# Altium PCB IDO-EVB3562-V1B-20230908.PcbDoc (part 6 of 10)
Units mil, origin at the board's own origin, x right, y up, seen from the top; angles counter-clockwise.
Board outline 5314.96 x 3543.31 mil, 4 copper layers (TOP, L2-VCC, L3-GND, BOTTOM), stack 28.8 mil thick; 747 components, 560 nets, 2514 pads, 1964 vias.
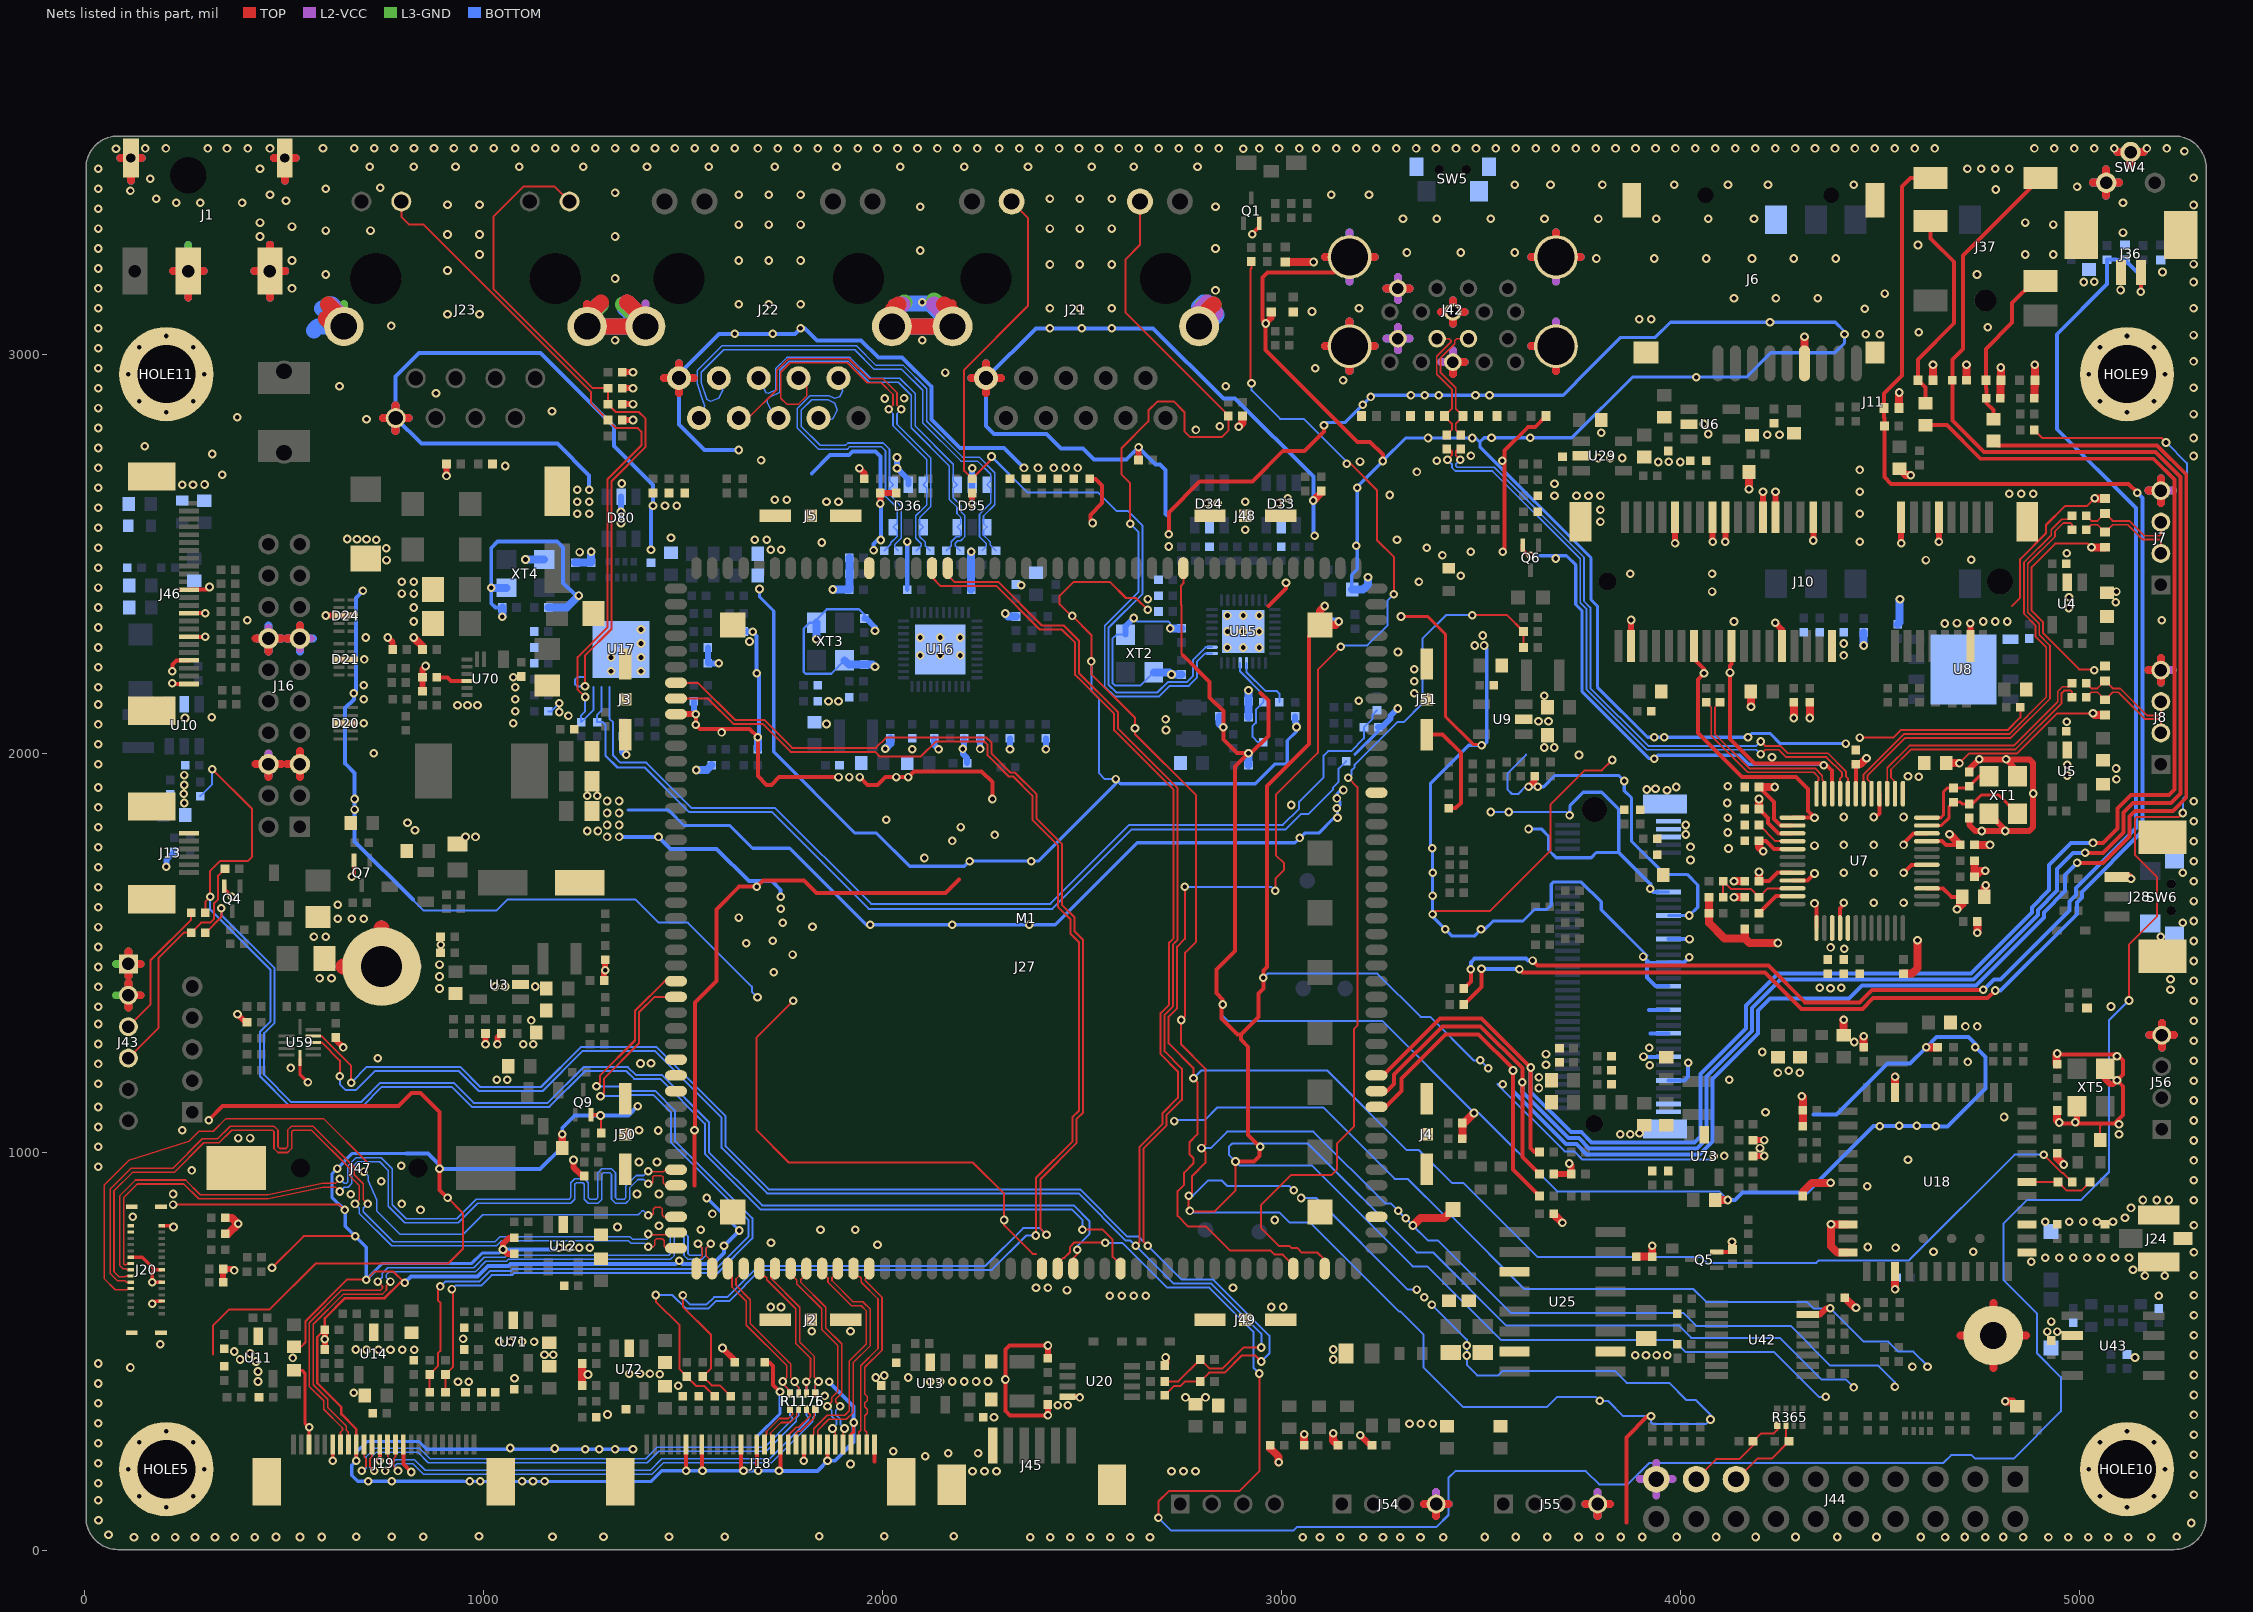
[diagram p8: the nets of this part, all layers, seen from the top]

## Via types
v1: diameter 21.65, hole 11.81, TOP to BOTTOM, 1964 vias

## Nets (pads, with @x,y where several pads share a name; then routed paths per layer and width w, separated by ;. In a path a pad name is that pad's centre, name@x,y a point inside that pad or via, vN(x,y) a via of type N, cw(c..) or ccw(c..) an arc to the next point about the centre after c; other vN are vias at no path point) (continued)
GND: (continued)
  other v1: 124.13,34.53 177,34.53 227,34.53 277,34.53 327,34.53 377,34.53 427,34.53 480,35 540,35 595,35 2371.05,34.53 2421.05,34.53 2471.05,34.53 2521.05,34.53 2571.05,34.53 2621.05,34.53 2671.05,34.53 3054.05,34.53 3097.05,34.53 3148,34.53 3205.25,34.53 3255.05,34.53 3298.05,34.53 3349,34.53 3406.25,34.53 3510,35 3588,35 3667,35 3745,35 3798,35 3851,35 3905,35 3991,35 4090,35 4189,35 4289,35 4394,35 4492,35 4603.11,35.17 4664.06,34.53 4713,35 4764.47,34.53 4810,35 4859.59,34.77 4923.11,34.53 4973.11,34.53 5023.11,34.53 5073.11,34.53 5123.11,34.53 5180.67,34.53 681,36 770,36 849,36 1173,36 1301,36 1465,36 1605,36 5245,36 989,37 1842,37 2005,37 2179,37 59.98,40.63 5281,70 34.99,77 34.53,127 5287.83,141.12 34.53,170 5287.83,191.12 2226,200 2256,200 2286,200 2725,200 2755,200 2785,200 1920,218 34.53,220 2107.72,237.28 5287.83,241.12 2165,245 2240,245 2027,250 1179,257 1067,258 34.53,270 5287.83,291.12 3321.35,318.65 3350,318.65 3380,318.65 34.53,320 2280,335 5287.83,341.12 1311,342 2440,365 2465,365 34.53,370 2760,385 2810,385 1855.47,388.7 5287.83,391.12 675,397 1488.67,414.39 34.53,420 936.32,424.4 962.97,424.4 435,425 2120,425 2145,425 2175,425 2205,425 2235,425 2265,425 1078,433 1983.32,435 2065,435 2005,440 5287.83,441.12 1442,443 1365.65,444.12 1392.3,444.12 1417.3,444.12 435,450 115,460 4582.2,462.01 34.53,470 430,475 390,480 3130,480 522,484 5140,485 3887.52,490.89 3914.18,490.88 3940.83,490.88 3967.49,490.68 5287.83,491.12 1153,492 1175,492 415,495 375,500 680,505 706.99,504.58 736.99,504.58 766.99,504.58 796.67,504.58 826.67,504.58 3130,505 190,518 1040,525 1066.99,524.58 1096.99,524.58 1126.99,524.58 949,532 5287.83,541.12 4920,550 4945,550 1823,551 1920,551 4930,575 5287.83,591.12 1720,611.58 1746,611.58 2975,611.58 3005,611.58 3358.48,636.38 2570,640 2600,640 2630,640 2660,640 5200,640 5287.83,641.12 2463,654 2385,660 2415,660 2879,660 5165,690 5215,690 5287.83,691.12 5135,705 4880,725 4915,735 4950,735 4985,735 5020,735 5055,735 5090,735 5125,735 5287.83,748.67 4635,750 4735,750 1215,760 1240,760 1266.79,760.14 4540,760 4470,762 1988,768 1721,773 1545,805 1845,805 1931.93,805 1336,812 1440,815 5287.83,816.39 4915,825 4975,825 5010,825 5045,825 5085,825 2984,829.67 5115,835 121,838 1574,845 842.17,855 5130,860 795,870 5287.15,879.12 5160,880 5195,880 5225,880 667.12,894.32 222.01,894.95 1385,895 1440,895 4469,914 743.69,926.98 5287.15,929.12 269,954 34.53,963 794.26,965.74 1390,975 1435,975 5287.15,979.12 4571,981 4110.37,990.37 4200,1010 34.53,1013 5287.15,1029.12 385,1035 415,1035 3850,1045 3875,1045 5100,1045 3898,1047 1438,1054 245,1055 1390,1055 34.53,1063 4549,1066 4593,1066 5100,1070 4990,1075 5287.15,1079.12 4812,1088 4214,1100 34.53,1113 5287.15,1129.12 3645.86,1160.68 34.53,1171 5287.15,1179.12 1033.35,1181.47 1060,1181.47 4123,1181 3645.86,1187.34 4245,1199 4300,1199 4272,1204 517,1211 3923.63,1217.35 3663.7,1219 34.53,1221 1393.55,1221.9 1420.19,1222.55 4721,1226 5287.15,1229.12 735,1235 5095,1240 3663.7,1245.65 4206,1251 3922.47,1261.67 1100,1270 1125,1270 34.53,1271 4436,1276 5287.15,1279.12 4715,1315 4745,1315 34.53,1321 5287.15,1329.12 1120,1330 34.53,1364 5080,1365 5287.15,1379.12 5229,1406.91 890,1410 4376.98,1411 4350,1411.6 4404.04,1411.6 34.53,1414 1030,1415 1055,1415 1130,1415 5287.15,1429.12 5229,1433.57 589.25,1435.77 619.25,1435.77 890,1440 1727.4,1450.94 34.53,1464 890,1470 5287.15,1479.12 1775,1495 34.53,1514 893,1520 1658.62,1523.19 5287.15,1529.12 1725.27,1530 575,1540 605,1540 5205,1540 34.53,1564 1825,1565 1750.12,1575 5260,1575 5287.15,1579.12 635,1585 670,1585 700,1585 1640,1587.83 1745,1610 34.53,1614 635,1620 4485,1625 4560,1625 5287.15,1629.12 34.53,1664 5287.15,1679.12 4410,1700 4485,1700 5260,1700 34.53,1714 5287.15,1729.12 4026,1732 2105.41,1737 4121,1761 34.53,1764 4026,1765 4336.7,1768.3 4410,1770 4485,1770 5287.15,1779.12 2175,1780 955,1790 980,1790 1310,1790 2281.5,1795 4014,1796 4119,1801 1260,1805 1287,1805 828.5,1806.87 34.53,1814 2196.24,1814.69 1310,1820 1340,1820 4014,1820 809.65,1825.71 5287.15,1829.12 2009.43,1832.83 4119,1838 4410,1840 4560,1840 1310,1850 1340,1850 3139,1862 34.53,1864 3025,1870 250,1875 4118,1875 5287.15,1879.12 1310,1880 1340,1880 1260,1893 1285,1893 249,1898 3967,1907 3916,1909 3938,1911 34.53,1914 3990,1915 3643,1916 4119,1917 250,1920 5093.53,1934.47 1916.65,1940 4970,1944.02 250,1945 5092.72,1961.69 4970,1970.67 34.53,1972 4230,1990 3746.33,1995.33 725,2000 2075,2010 3659,2014 3684,2014 34.53,2022 1597,2052 2711,2058.06 34.53,2072 1860,2073 700,2075 1075,2075 4969,2079 3645,2080 3670,2080 2709.98,2084.69 252,2088 319,2090 1213,2094 1190.01,2103.32 1080,2105 935,2120 960,2120 985,2120 34.53,2122 1865,2130 1890,2130 3194.45,2131.6 700,2135 1080,2135 3659,2144 3333.42,2150 34.53,2165 1080,2165 700,2170 3333.42,2180 1075,2190 1320,2205 1395,2205 3333.42,2210 34.53,2215 701,2235 1320,2240 1395,2240 2095,2245 2145,2245 2195,2245 4410,2245 3292.68,2253.69 34.53,2265 2865,2265 2905,2265 2945,2265 3485,2270 1395,2275 4410,2275 1667,2280 705,2290 2095,2290 2145,2290 2195,2290 3505,2295 2865,2305 2905,2305 2945,2305 1395,2310 34.53,2315 4663,2325 4694,2326 825,2330 4135,2330 4760,2330 4790,2330 4820,2330 408.13,2333.04 5207,2333 2865,2345 2905,2345 2945,2345 4973.98,2364.03 34.53,2365 825,2365 5092,2378.39 2665.57,2386.24 4974.73,2390.67 795,2400 825,2400 4080,2405 5093.53,2405 34.53,2415 2348,2421 795,2430 825,2430 3345,2430 3450,2445 3875,2450 4080,2450 34.53,2465 757,2484 4616,2484 4730,2485 3688,2488 3404,2496 4969,2501 1241,2504 3475,2505 1720,2510 1746.65,2510 756,2514 34.53,2515 3365,2515 2718,2518 3188,2520 1848,2528 4450,2530 731,2535 1680,2535 1710,2535 3290,2535 683,2536 707,2536 658.69,2536.69 1470,2540 2910,2560 34.53,2565 3800,2580 1235,2600 1265,2600 4450,2600 3800,2610 34.53,2615 1455,2620 1484.4,2620 2813.45,2626.58 2840.11,2626.64 2992.39,2626.58 1235,2630 1265,2630 1860,2630 1890,2630 2910,2630 1730,2635 1760,2635 3015.93,2639.07 3685,2645 3740,2645 3770,2645 3800,2645 3272,2647 4825,2650 4855,2650 4885,2650 4450,2655 1235,2660 34.53,2665 245,2673 272,2673 301,2673.36 3685,2675 1347,2676 345,2698 3340,2705 4450,2710 34.53,2715 2390,2715 2430,2715 2460,2715 2490,2715 1055,2720 3945,2730 3971.65,2730.2 4000,2730 3197.22,2730.87 3390,2733.18 3554,2733 1696,2734 3795,2740 3825,2740 3855,2740 3475.41,2745.24 5287,2745 320,2750 34.53,2765 151,2769 5287,2790 4218,2798 4249,2798 4070,2800 3802,2803 2786.05,2810.32 34.53,2815 2845.64,2819.36 4059.33,2825 707,2837 383,2842 5287,2850 1172,2857 34.53,2865 2006,2889 2054.48,2890 881,2902 34.53,2915 5287,2916 639,2920 2861,2920 3155,2935 2158,2954 34.53,2965 3085,2965 5287,2982 34.53,3015 5287,3048 4465,3050 4500,3050 4598,3055 34.53,3065 4771,3068 769,3071 3897.26,3087.74 3927.26,3087.74 910,3100 990,3100 3077,3107 4463,3114 34.53,3115 2420,3115 2495,3115 2575,3115 3195,3115 5287,3115 1640,3125 1715,3125 1795,3125 4135,3140 4240,3140 4345,3140 4513,3152 5104,3161 34.53,3165 520,3165 5012,3181 5287,3181 5038,3182 4744,3200 5209,3206 910,3210 34.53,3215 2420,3225 2495,3225 2575,3225 5287,3226 520,3235 1640,3235 1715,3235 1795,3235 3790,3240 3935,3240 4065,3240 4180,3240 4285,3240 4390,3240 990,3250 4865,3250 4935,3250 3315,3255 3450,3255 3585,3255 34.53,3265 4596,3274 440,3295 910,3300 990,3300 5110,3305 717,3310 34.53,3315 2420,3315 2495,3315 2575,3315 520,3320 1640,3325 1715,3325 1795,3325 4935,3325 440,3330 4865,3330 3305,3340 3390,3340 3525,3340 3660,3340 3795,3340 3940,3340 4070,3340 4185,3340 34.53,3365 5287,3374 910,3375 990,3375 230,3380 290,3380 395,3380 5110,3380 505,3385 180,3390 2420,3390 2495,3390 2575,3390 465,3400 1640,3400 1715,3400 1795,3400 3125,3400 3220,3400 115,3410 4791,3413 34.53,3415 741,3417 4995,3420 3585,3425 3675,3425 3805,3425 3985,3425 4120,3425 4220,3425 4435,3425 165,3440 5287,3442 34.53,3465 440,3465 4720,3465 4755,3465 4790,3465 4825,3465 5264,3509 79,3515 2905,3515 152,3516 204,3516 309,3516 357,3516 409,3516 465,3516 2945,3516 2995,3516 3045,3516 3088,3516 3138,3516 3188,3516 3238,3516 3288,3516 3338,3516 3388,3516 3438,3516 3488,3516 3538,3516 3588,3516 3638,3516 3688,3516 3738,3516 3788,3516 3838,3516 3888,3516 3938,3516 3988,3516 4038,3516 4088,3516 4138,3516 4188,3516 4238,3516 4288,3516 4338,3516 4388,3516 4438,3516 4488,3516 4538,3516 4588,3516 4638,3516 4888,3516 4938,3516 4988,3516 5038,3516 5088,3516 5170,3516 5220,3516
GND_EARTH: HOLE5.1 HOLE9.1 HOLE10.1 HOLE11.1 J21.SH1 J21.SH2 J22.SH1 J22.SH2 J23.13 J23.14 | length 3703.1
  TOP w20: J23.13@1259.92,3094.92 1259.92,3126.14 ; J22.SH2@2023.9,3108.9 2023.9,3126.9 ; J21.SH1@2176.1,3103.9 2176.1,3126.9
  TOP w40: 605,3090 625.08,3069.92 J23.14@650.08,3069.92 650.08,3084.92 610,3125 ; J23.13@1259.92,3069.92 1259.92,3094.92 1295,3130 ; J23.13@1259.92,3069.92 J22.SH1@1406.1,3069.9 1406.1,3083.9 1360,3130 ; 2040,3125 2023.9,3108.9 J22.SH2@2023.9,3069.9 J21.SH1@2176.1,3069.9 2176.1,3103.9 2155,3125 ; J21.SH2@2793.9,3069.9 2793.9,3088.9 2830,3125
  L2-VCC w20: J22.SH1@1406.1,3083.9 1406.1,3126.9
  L2-VCC w40: 615,3125 650.08,3089.92 J23.14@650.08,3069.92 ; 1290,3125 1259.92,3094.92 J23.13@1259.92,3069.92 J22.SH1@1406.1,3069.9 1406.1,3083.9 1360,3130 ; 2050,3125 2023.9,3098.9 J22.SH2@2023.9,3069.9 J21.SH1@2176.1,3069.9 2176.1,3078.9 2130,3125 ; 2815,3130 2793.9,3108.9 J21.SH2@2793.9,3069.9 2799.9,3069.9 2835,3105
  L3-GND w20: J23.14@650.08,3084.92 650.08,3126.14 ; J21.SH2@2793.9,3088.9 2793.9,3126.9
  L3-GND w40: 605,3090 625.08,3069.92 J23.14@650.08,3069.92 650.08,3084.92 610,3125 ; 1295,3125 1259.92,3089.92 J23.13@1259.92,3069.92 J22.SH1@1406.1,3069.9 1405.1,3069.9 1350,3125 ; 2055,3130 2023.9,3098.9 J22.SH2@2023.9,3069.9 J21.SH1@2176.1,3069.9 2176.1,3088.9 2130,3135 ; J21.SH2@2793.9,3069.9 2793.9,3088.9 2830,3125
  BOTTOM w20: J23.13@1259.92,3094.92 1259.92,3126.14 ; 1349.1,3069.9 J22.SH1@1400.1,3069.9 ; J22.SH2@2023.9,3098.9 2023.9,3126.9
  BOTTOM w40: 575,3060 584.92,3069.92 J23.14@640.08,3069.92 ; 595,3115 J23.14@640.08,3069.92 ; 620,3125 650.08,3094.92 J23.14@650.08,3069.92 J23.14@640.08,3069.92 ; 1290,3125 1259.92,3094.92 J23.13@1259.92,3069.92 J22.SH1@1406.1,3069.9 1400.1,3069.9 1355,3115 ; 2805,3130 2793.9,3118.9 J21.SH2@2793.9,3069.9 ; J21.SH2@2793.9,3069.9 2809.9,3069.9 2838.18,3098.18 2838.18,3099.6 2831.6,3106.18 2830.18,3106.18 J21.SH2@2793.9,3069.9 ; J22.SH2@2023.9,3069.9 2023.9,3098.9 2052.19,3127.19 2118.81,3127.19 J21.SH1@2176.1,3069.9 J22.SH2@2023.9,3069.9
  other v1: 1330,3035 2100,3035 2100,3130 2835,3160 1330,3190 605,3200 2095,3260 2835,3265 1330,3295 605,3310 2095,3370 2835,3370 1330,3405 605,3415 715,3470 825,3470 930,3470 1090,3470 1250,3470 1410,3470 1565,3470 1730,3470 1885,3470 2045,3470 2205,3470 2365,3470 2525,3470 2630,3470 2790,3470 597.82,3516.18 676,3516.18 726,3516.18 776,3516.18 826,3516.18 876,3516.18 926,3516.18 976,3516.18 1026,3516.18 1080,3516.18 1130,3516.18 1180,3516.18 1230,3516.18 1280,3516.18 1330,3516.18 1380,3516.18 1430,3516.18 1480,3516.18 1530,3516.18 1580,3516.18 1630,3516.18 1688,3516 1738,3516 1788,3516 1838,3516 1888,3516 1938,3516 1988,3516 2038,3516 2088,3516 2138,3516 2188,3516 2238,3516 2293,3516 2343,3516 2393,3516 2443,3516 2493,3516 2543,3516 2593,3516 2643,3516 2693,3516 2743,3516 2793,3516 2843,3516
GPIO0_A5_D: M1.170 R429.2 R430.2 | length 2282.1
  TOP w5: M1.170@3108.86,707.87 3108.86,729.93 3090.78,748 3051.86,748 3040.86,759 3026,759 3021,764 2995,764 2949,810 2949,867 3024,942 3125,942 3140,957 3140,1022 3182,1064 3182,1308 3191,1317 3191,1915 v1(3168,1938) ; v1(3479,2346) 3566.28,2346 R429.2@3607.28,2305 R430.2@3607.28,2265
  BOTTOM w5: v1(3168,1938) 3176,1946 3176,1957 3184,1965 3184,1971 3291,2078 3307,2078 3353.5,2124.5 3353.5,2286.5 3413,2346 v1(3479,2346)
HOST_WAKE_BT_H: R237.2 R1174.1 U18.6 | length 175.3
  TOP w5: U18.6@4869.41,925 R237.2@4947.28,925 4968.28,904 5006.28,904 R1174.1@5027.28,925
HOST_WAKE_BT_H_GPIO0_A7_D: M1.168 R237.1 R1173.2 | length 5978.1
  TOP w5: v1(2758.33,1665) 2758.33,1534.33 2738.8,1514.8 2738.8,1360.86 2717.67,1339.74 2717.67,1272.75 2780,1210.42 v1(2780,1185) 2789.55,1175.45 2789.55,1044.56 2770,1025 2770,995 2780,985 2780,971.57 2756.68,948.25 2756.68,918.53 2740.03,901.87 2740.03,839.98 2766,814 2811,814 2872.07,752.93 2973.21,752.93 2983.21,742.93 3004.07,742.93 3030.12,716.88 M1.168@3030.12,707.87 ; R1173.2@2925,3232.28 2925,3215.13 2922.3,3212.42 2922.3,2930.22 v1(2925.51,2927) ; v1(2984.98,1655) 2984.98,1684.98 3007.39,1707.39 3007.39,1723.61 2986.65,1744.35 2986.65,1895.98 3091.64,2000.96 3091.64,2209.07 v1(3148.99,2266.43) ; v1(3164.36,2725.29) 3173.71,2725.29 3240,2659 3240,2534 3282,2492 v1(3282,2398) ; v1(4911.18,993.38) 4957.55,947 4960.72,947 R237.1@4982.72,925
  BOTTOM w5: v1(2758.33,1665) 2974.98,1665 v1(2984.98,1655) ; v1(2780,1185) 2800,1205 3114.57,1205 3314.57,1005 3345.3,1005 3428.12,922.17 3457.3,922.17 3642.79,736.67 4051.48,736.67 4065.95,722.21 4341.59,722.21 4347.6,728.22 4573.22,728.22 4838.38,993.38 v1(4911.18,993.38) ; v1(2925.51,2927) 2925.51,2909.49 2997,2838 3056.51,2838 3164.36,2730.15 v1(3164.36,2725.29) ; v1(3148.99,2266.43) 3152.56,2270 3216.04,2270 3266.75,2320.71 3266.75,2382.75 v1(3282,2398)
HP_DET_L_GPIO0_B3_D: M1.153 R455.1 | length 7025.2
  TOP w5: M1.153@2439.57,707.87 2439.57,721.57 2453,735 2456.11,735 2470.55,749.44 2470.55,762.59 2481.28,773.33 2558.32,773.33 v1(2559.02,772.63) ; v1(2692,83) 2692,124 2718,150 2895,150 2945,200 v1(2945,445) ; R455.1@4887.72,2810 4907.72,2790 5206.88,2790 v1(5218,2778.88) ; v1(5125,1380) 5125,1520 5195,1590 5195,1690 5140,1745 5140,1835 5145,1840 5250,1840 v1(5260,1850)
  BOTTOM w5: v1(2559.02,772.63) 2601.37,772.63 2714,660 2820,660 2930,550 2930,460 v1(2945,445) ; v1(2692,83) 2723.41,51.59 3031.14,51.59 3040.24,60.69 3389.69,60.69 3419.23,90.23 3419.23,183.23 3436.33,200.33 3763.71,200.33 3797.04,167 3869.07,167 3923.03,220.97 4660.11,220.97 4679.14,240 4730.8,240 4739.12,231.67 4827.49,231.67 4835.78,231.67 4954.15,350.05 4954.15,435.85 4895,495 4895,595 4810,680 4810,820 4870,880 5005,880 5075,950 5075,1330 v1(5125,1380) ; v1(5218,2778.88) 5270,2726.88 5270,1895 5260,1885 v1(5260,1850)
HP_SNS: J37.4 M1.11 R306.1 R316.2 | length 5192.3
  TOP w10: M1.11@3238.78,1152.76 3264.87,1152.76 3283,1170.89 3283,1193.98 3404.02,1315 3500,1315 3604.21,1210.79 v1(3604.21,1175.3) 3604.21,988.07 R306.1@3647.28,945 ; J37.4@4903.39,3441.73 4709,3247.34 4709,3013 4682.28,2986.28 R316.2@4682.28,2935 4682.28,2833.57 4761.15,2754.69 5191.52,2754.69 5253.62,2692.59 5253.62,1898.62 5230,1875 5135,1875 5111,1851 5111,1801 5060,1750 v1(5015,1750)
  BOTTOM w10: v1(3604.21,1175.3) 3604.21,1150.79 3720.24,1034.76 3745.81,1034.76 3771.68,1008.9 4042.23,1008.9 4066.06,1032.73 4066.06,1189.85 4180,1303.79 4180,1361.21 4251.22,1432.43 4735.11,1432.43 4896.44,1593.76 4896.44,1606.77 4945,1655.33 4945,1710 4985,1750 v1(5015,1750)
HPL_OUT: C215.1 C222.2 M1.10 | length 4508.9
  TOP w10: M1.10@3238.78,1113.39 3261.87,1113.39 3301,1152.52 3301,1183.87 3412.13,1295 3495,1295 3581.04,1208.96 v1(3581.04,1204.5) 3581.04,956.24 C215.1@3647.28,890.01 ; C222.2@4785,2782.44 4795.75,2771.69 5195.74,2771.69 5268.62,2698.81 5268.62,1888.62 5235,1855 5140,1855 5126,1841 5126,1790.57 5060.43,1725 v1(4995,1725)
  BOTTOM w10: v1(3581.04,1204.5) 3581.04,1152.74 3714.02,1019.76 3739.6,1019.76 3765.46,993.9 4048.44,993.9 4081.06,1026.51 4081.06,1183.63 4195,1297.57 4195,1355 4225,1385 4423,1385 4455.43,1417.43 4741.32,1417.43 4911.44,1587.55 4911.44,1600.56 4965,1654.12 4965,1695 v1(4995,1725)
HPL_OUT+: C222.1 D66.1 J37.2 R447.2 | length 420.1
  TOP w10: C222.1@4785,2837.56 4785,2860 4767.28,2877.72 R447.2@4767.28,2890 4767.28,2912.72 4766.1,2913.9 D66.1@4766.1,2935 4766.1,3013.1 4832,3079 4832,3128 4887.86,3183.86 J37.2@4903.39,3183.86
HPR_OUT: C219.1 C224.2 M1.12 | length 4476.1
  TOP w10: M1.12@3238.78,1192.13 3255.13,1192.13 3398,1335 3502.18,1335 v1(3625.09,1212.09) 3625.09,1191.26 3625.04,1191.21 3625.04,1010.01 3635.04,1000.01 C219.1@3647.28,1000.01 ; C224.2@4615,2822.44 4668.56,2822.44 4753,2738 5187,2738 5238.62,2686.38 5238.62,1908.62 5225,1895 5130,1895 5096,1861 5096,1811 5060,1775 v1(5035,1775)
  BOTTOM w10: v1(3625.09,1212.09) 3625.09,1210.09 3625.04,1210.04 3625.04,1151.17 3726.45,1049.76 3752.03,1049.76 3777.89,1023.9 4036.02,1023.9 4051.06,1038.94 4051.06,1196.06 4165,1310 4165,1367.43 4245,1447.43 4728.89,1447.43 4881.44,1599.98 4881.44,1612.99 4925,1656.55 4925,1720 4980,1775 v1(5035,1775)
HPR_OUT+: C224.1 D68.1 J37.3 | length 526.1
  TOP w10: C224.1@4615,2877.56 4615,2916.1 D68.1@4596.1,2935 4596.1,2987.1 4687,3078 4687,3231 4627.36,3290.64 J37.3@4627.36,3333.46
HUB_1V8: C303.2 C305.2 C310.2 C355.2 U7.3 U7.9 U7.26 U7.29 | length 571.4
  TOP w10: C310.2@4197.72,1780 4215,1780 4235.5,1759.5 U7.29@4281.7,1759.5 ; C305.2@4197.72,1915 4235,1877.72 4235,1835 4251.4,1818.6 U7.26@4281.7,1818.6 ; U7.3@4618.3,1661.1 4658.9,1661.1 4680,1640 C355.2@4707.44,1640 ; U7.9@4618.3,1779.2 4656.8,1779.2 4666,1770 4702,1770 C303.2@4702.28,1770
  TOP w20: C310.2@4197.72,1780 4197.72,1764.28 v1(4208,1754) ; C305.2@4197.72,1915 v1(4237,1915) ; v1(4675,1797) C303.2@4702,1770 ; v1(4694,1609) 4707.44,1622.44 C355.2@4707.44,1640
HUB_3V3: C304.2 C306.2 C307.1 C308.1 C309.1 C356.2 R45.2 R48.1 R434.1 R435.1 R436.1 R438.2 R439.2 U7.13 U7.19 U7.27 U7.32 U7.39 U7.41 | length 858.2
  TOP w10: C306.2@4197.72,1679 4223,1679 4244.5,1700.5 U7.32@4281.7,1700.5 ; C308.1@4197.72,1860 4220,1837.72 4220,1825 4246.1,1798.9 U7.27@4281.7,1798.9 ; C309.1@4440,1972.28 4440.2,1972.08 U7.19@4440.2,1898.3
  TOP w20: R45.2@4072.28,1639 R48.1@4072.28,1599 4072.28,1574.72 4111.28,1535.72 4162.28,1535.72 ; R438.2@4162.28,1559 4162.28,1535.72 ; C306.2@4197.72,1679 v1(4197.72,1702) ; C308.1@4197.72,1860 v1(4197.72,1885) ; v1(4245,1524) 4174,1524 4162.28,1535.72 ; C309.1@4440,1972.28 4452.28,1972.28 v1(4467,1987) ; R439.2@4560,1447.28 4581.28,1447.28 4595,1461 v1(4595,1531) ; R436.1@4737.72,1730 R435.1@4737.72,1690 4752.72,1705 v1(4765,1705) ; v1(4744.72,1550) R434.1@4744.72,1578
  other v1: 4411,1510 4377,1513 4598,1941 4571,1942
HUB_DM1: R49.1 U7.23 | length 444.5
  TOP w4.5: R49.1@4100,2127.28 4087.25,2114.53 4087.25,2047.75 4173.25,1961.75 4338.25,1961.75 4356.3,1943.7 4356.3,1933.7 4361.4,1928.6 U7.23@4361.4,1898.3
HUB_DM2: R37.1 U7.20 | length 1606.8
  TOP w4.5: v1(3448.33,2735.6) 3437.25,2746.68 3437.25,2757.25 3442.28,2762.28 R37.1@3450,2762.28 ; v1(4201.77,2029.34) 4212.84,2018.27 4251.17,2018.27 4269.94,1999.5 4370.5,1999.5 4415.4,1954.6 4415.4,1941.83 4420.5,1936.73 U7.20@4420.5,1898.3
  BOTTOM w4.5: v1(3448.33,2735.6) 3437.25,2724.53 3437.25,2720.03 3440.78,2716.5 3533.5,2716.5 3758.84,2491.16 3758.84,2381.16 3775,2365 3775,2163 3919.73,2018.27 4190.69,2018.27 v1(4201.77,2029.34)
HUB_DM2_2: D8.2 J42.11 R37.2 | length 324.4
  TOP w4.5: R37.2@3450,2797.72 3437.25,2810.47 3437.25,2826.15 D8.2@3456.1,2845 3437.25,2863.85 3437.25,2916.19 3399.5,2953.94 3399.5,2990.83 3434.75,3026.08 3434.75,3034.52 3439.25,3039.02 J42.11@3469.37,3039.02
HUB_DM3: R29.1 U7.17 | length 1124
  TOP w4.5: U7.17@4479.5,1898.3 4479.5,1924.5 4469.3,1934.7 4469.3,1943.3 4564.32,2038.32 4828.49,2038.32 4927,2136.83 4927,2269.59 4900.06,2296.53 4900.06,2324.66 4871.35,2353.37 4871.35,2474.35 4939.5,2542.5 4939.5,2556.06 4960.34,2576.9 4979.1,2576.9 4982.28,2573.72 R29.1@4982.28,2560
HUB_DM3_2: D4.2 J7.2 R29.2 | length 255.7
  TOP w4.5: R29.2@5017.72,2560 5030.47,2572.75 5046.15,2572.75 D4.2@5065,2553.9 5083.85,2572.75 5122.25,2572.75 5159.75,2535.25 5200.5,2535.25 5205,2530.75 J7.2@5205,2500.63
HUB_DM4: R32.1 U7.14 | length 630.9
  TOP w4.5: U7.14@4538.6,1898.3 4538.6,1928.4 4528.4,1938.6 4528.4,1958.96 4578.75,2009.32 4840.5,2009.32 4956,2124.82 4956,2150.56 4962.34,2156.9 4979.1,2156.9 4982.28,2153.72 R32.1@4982.28,2140
HUB_DM4_2: D6.2 J8.2 R32.2 | length 268.1
  TOP w4.5: R32.2@5017.72,2140 5030.47,2152.75 5046.15,2152.75 D6.2@5065,2133.9 5083.85,2152.75 5098.5,2152.75 5166,2085.25 5200.5,2085.25 5205,2080.75 J8.2@5205,2050.63
HUB_DP1: R50.1 U7.24 | length 444.5
  TOP w4.5: R50.1@4065,2127.28 4077.75,2114.53 4077.75,2043.81 4169.31,1952.25 4334.31,1952.25 4346.8,1939.77 4346.8,1931.8 4341.7,1926.7 U7.24@4341.7,1898.3
HUB_DP2: R38.1 U7.21 | length 1606.8
  TOP w4.5: R38.1@3415,2762.28 3422.72,2762.28 3427.75,2757.25 3427.75,2746.68 v1(3416.67,2735.6) ; v1(4201.77,1997.69) 4212.84,2008.77 4247.23,2008.77 4266,1990 4366.56,1990 4405.9,1950.67 4405.9,1941.83 4400.8,1936.73 U7.21@4400.8,1898.3
  BOTTOM w4.5: v1(3416.67,2735.6) 3427.75,2724.53 3427.75,2716.09 3436.84,2707 3529.56,2707 3749.34,2487.23 3749.34,2377.23 3765.5,2361.06 3765.5,2159.06 3915.8,2008.77 4190.69,2008.77 v1(4201.77,1997.69)
HUB_DP2_2: D9.1 J42.12 R38.2 | length 324.4
  TOP w4.5: J42.12@3390.63,3039.02 3420.75,3039.02 3425.25,3034.52 3425.25,3030.01 3390,2994.76 3390,2950 3427.75,2912.25 3427.75,2863.85 D9.1@3408.9,2845 3427.75,2826.15 3427.75,2810.47 R38.2@3415,2797.72
HUB_DP3: R30.1 U7.18 | length 1124.1
  TOP w4.5: U7.18@4459.8,1898.3 4459.8,1947.23 4560.38,2047.82 4824.55,2047.82 4917.5,2140.77 4917.5,2265.65 4890.56,2292.59 4890.56,2320.72 4861.85,2349.43 4861.85,2478.28 4930,2546.44 4930,2560 4956.4,2586.4 4973.68,2586.4 R30.1@4982.28,2595
HUB_DP3_2: D5.1 J7.3 R30.2 | length 255.7
  TOP w4.5: R30.2@5017.72,2595 5030.47,2582.25 5046.15,2582.25 D5.1@5065,2601.1 5083.85,2582.25 5126.19,2582.25 5163.69,2544.75 5200.5,2544.75 5205,2549.25 J7.3@5205,2579.37
HUB_DP4: R33.1 U7.15 | length 630.9
  TOP w4.5: U7.15@4518.9,1898.3 4518.9,1962.9 4574.82,2018.82 4836.56,2018.82 4946.5,2128.75 4946.5,2154.5 4958.4,2166.4 4973.68,2166.4 R33.1@4982.28,2175
HUB_DP4_2: D7.1 J8.3 R33.2 | length 268.1
  TOP w4.5: R33.2@5017.72,2175 5030.47,2162.25 5046.15,2162.25 D7.1@5065,2181.1 5083.85,2162.25 5102.44,2162.25 5169.94,2094.75 5200.5,2094.75 5205,2099.25 J8.3@5205,2129.37
HUB_REXT: R47.1 U7.28 | length 100.9
  TOP w5: R47.1@4197.72,1820 4238.52,1779.2 U7.28@4281.7,1779.2
HUB_VBUSM: R437.1 U7.35 | length 101.5
  TOP w10: R437.1@4197.72,1599 4240.12,1641.4 U7.35@4281.7,1641.4
HUB_XIN: C54.1 R43.2 U7.12 XT1.3 | length 233.3
  TOP w8: U7.12@4618.3,1838.3 4653.3,1838.3 4660,1845 4660,1903 4669.72,1912.72 R43.2@4685,1912.72 4720.44,1912.72 C54.1@4725,1917.28 4749.96,1942.24 XT1.3@4774.57,1942.24
HUB_XOUT: C53.2 R43.1 U7.11 XT1.1 | length 298.7
  TOP w8: U7.11@4618.3,1818.6 4654.6,1818.6 4674,1838 4674,1866.28 R43.1@4685,1877.28 4702.72,1877.28 4707.28,1872.72 C53.2@4725,1872.72 4732.72,1872.72 4755,1895 4798.19,1895 XT1.1@4845.43,1847.76
HUB_XRSTJ: C311.2 R36.2 R45.1 U7.34 | length 239.7
  TOP w5: R45.1@4107.72,1639 R36.2@4107.72,1679 4127.72,1659 4177.72,1659 C311.2@4197.72,1639 4219.82,1661.1 U7.34@4281.7,1661.1
I2C1_SCL_M1: M1.112 R15.2 R128.1 | length 2058.3
  TOP w5: R128.1@905,397.72 R15.2@905,442.28 923.35,460.63 923.35,654.13 v1(920.94,656.54) ; v1(1283.42,1164.83) 1291.75,1173.15 1291.75,1191.36 1380,1279.61 1380,1354.14 1454.2,1428.35 M1.112@1482.87,1428.35
  BOTTOM w5: v1(920.94,656.54) 929.75,665.35 994.12,665.35 1020.28,691.5 1072.2,691.5 1077.2,696.5 1586.76,696.5 1673.93,783.66 1673.93,834.36 1480,1028.29 1480,1103.81 1430.33,1153.48 1365.33,1153.48 1353.99,1164.83 v1(1283.42,1164.83)
I2C1_SDA_M1: M1.113 R16.2 R129.1 | length 2052.4
  TOP w5: R129.1@865,397.72 R16.2@865,442.28 885.82,463.1 885.82,495.82 891.86,501.86 891.86,622.4 885.82,628.44 885.82,657.05 v1(891.94,663.17) ; v1(1293.42,1140.12) 1301.75,1148.44 1301.75,1184.31 1390,1272.56 1390,1350 1428.98,1388.98 M1.113@1482.87,1388.98
  BOTTOM w5: v1(891.94,663.17) 904.11,675.35 989.98,675.35 1016.14,701.5 1068.06,701.5 1073.06,706.5 1582.62,706.5 1663.93,787.81 1663.93,830.22 1470,1024.14 1470,1099.66 1426.18,1143.48 1353.48,1143.48 1350.12,1140.12 v1(1293.42,1140.12)
I2C2_SCL_M1: M1.93 R13.2 R126.1 | length 3602.5
  TOP w5: M1.93@1482.87,2176.38 1537.51,2176.38 1630.56,2083.33 1704.06,2083.33 1774.06,2013.33 1983.66,2013.33 2009.26,2038.93 2261.07,2038.93 2274,2026 2274,1998.55 2321.05,1951.5 2332.41,1951.5 2386,1897.91 2386,1836.89 2450.74,1772.14 2450.74,1619.26 2481.69,1588.31 2481.69,1553.16 2503,1531.86 2503,1099 2487,1083 2487,1023 2396.53,932.54 2396.53,807.91 v1(2411.53,792.91) ; v1(1500.01,641.4) 1500.01,612.63 1570,542.63 1570,457.28 R13.2@1550,437.28 1572.28,415 1592.72,415 R126.1@1620,387.72
  BOTTOM w5: v1(1500.01,641.4) 1500.01,635.75 1518.44,617.32 1559.04,617.32 1578.22,636.5 1611.62,636.5 1689.95,714.83 2258.59,714.83 2352.98,809.22 2395.22,809.22 v1(2411.53,792.91)
I2C2_SDA_M1: M1.94 R14.2 R127.1 | length 3606.6
  TOP w5: v1(1432,641.52) 1432,625 1491.65,565.35 1491.65,455.63 R14.2@1510,437.28 1533.64,413.64 1554.08,413.64 R127.1@1580,387.72 ; M1.94@1482.87,2137.01 1562.73,2137.01 1626.41,2073.33 1699.91,2073.33 1769.91,2003.33 1981.67,2003.33 1993.33,1991.67 2096.74,1991.67 2133.99,2028.93 2256.07,2028.93 2264,2021 2264,1994.4 2316.91,1941.5 2328.27,1941.5 2376,1893.77 2376,1832.74 2440.74,1768 2440.74,1614.26 2471.69,1583.31 2471.69,1547.31 2493,1526 2493,1104 2477,1088 2477,1027.15 2384.89,935.03 v1(2384.89,790.9)
  BOTTOM w5: v1(1432,641.52) 1473.96,641.52 1508.16,607.32 1563.18,607.32 1582.36,626.5 1615.76,626.5 1694.1,704.83 2274.51,704.83 2360.57,790.9 v1(2384.89,790.9)
I2C3_SCL_M0: M1.71 R12.2 R343.1 U59.9 | length 5351.4
  TOP w5: U59.9@573.47,1275 594.14,1275 640,1229.14 v1(640,1190) ; M1.71@2124.61,2463.78 2124.61,2440.39 2146.28,2418.72 2286.28,2418.72 2395,2310 2450,2310 2483,2277 2483,2196.42 2489.64,2189.78 2581,2098.42 2581,2057.33 2730,1908.33 2730,1900.05 2730,1536.14 2718.8,1524.94 2718.8,1369.15 2697.67,1348.02 2697.67,1245.33 2741,1202 2741,1136 2701.67,1096.67 2701.67,1069.96 2645,1013.29 2645,943.08 ; v1(2635,765) 2645,775 2645,943.07 ; R343.1@2707.72,425 2742.28,425 R12.2@2797.28,480 2820.28,457 2852,457 2905,510 v1(2950,510)
  BOTTOM w5: v1(640,1190) 640,1170 654.66,1155.34 680.34,1155.34 728.33,1203.33 937.53,1203.33 987.71,1153.14 1148.44,1153.14 1248.97,1253.67 1429.13,1253.67 1596.91,1085.9 1596.91,1010.38 1710.96,896.33 2491.82,896.33 2610.18,777.96 2622.04,777.96 v1(2635,765) 2730,670 2825,670 2950,545 v1(2950,510)
I2C3_SDA_M0: M1.70 R11.2 R344.1 U59.10 | length 5365.5
  TOP w5: U59.10@573.47,1290.75 594.23,1290.75 668.31,1216.67 v1(668.31,1173.67) ; M1.70@2163.98,2463.78 2163.98,2446.02 2181.28,2428.72 2291.28,2428.72 2400,2320 2455,2320 2493,2282 2493,2200.56 2587.5,2106.06 2591,2102.56 2591,2061.47 2740,1912.47 2740,1895.9 2740,1532 2734.14,1526.14 2728.8,1520.8 2728.8,1365.01 2707.67,1343.88 2707.67,1252.33 2751,1209 2751,1131 2712,1092 2712,1066.14 2655,1009.14 2655,938.93 2655,775 v1(2665,765) ; R344.1@2707.72,390 2730.72,413 2747,413 2759,425 R11.2@2797.28,425 2819.28,447 2858,447 2901,490 2935,490 v1(2950,475)
  BOTTOM w5: v1(668.31,1173.67) 707.97,1213.33 941.67,1213.33 991.86,1163.14 1144.3,1163.14 1244.83,1263.67 1433.28,1263.67 1606.91,1090.04 1606.91,1014.52 1715.1,906.33 2495.96,906.33 2614.33,787.96 2642.04,787.96 v1(2665,765) 2750,680 2830,680 2970,540 2970,495 v1(2950,475)
I2C5_SCL_M0/UART9_TX_M1: J44.15 R365.6 R425.2 | length 215.5
  TOP w5: J44.15@4140,180 4142.28,180 4193.64,231.36 4229.08,231.36 R425.2@4272.72,275 4265.16,282.56 R365.6@4265.16,315.31
I2C5_SDA_M0/UART9_RX_M1: J44.17 R365.5 R426.2 | length 272.3
  TOP w5: J44.17@4040,180 4090,230 4147.72,230 4182.72,265 R426.2@4182.72,275 4202.72,295 4235,295 4243.5,303.5 R365.5@4243.5,315.31
ILMT: R785.2 U70.10 | length 79.8
  TOP w10: R785.2@882.72,2190 910,2190 918.86,2181.14 U70.10@958.82,2181.14
ISOLATEB: R156.2 U15.20 | length 149
  BOTTOM w5: U15.20@2912.87,2226.26 2912.87,2203.13 2960,2156 2988,2156 2995,2149 R156.2@2995,2127.72
LAN0_A+: D36.6 J22.2 R169.2 | length 753.5
  BOTTOM w4: J22.2@1890,2940 1894.66,2926.01 1900.6,2908.2 1893.4,2893.8 1879.61,2889.2 1866.02,2896 1818.86,2896 1787,2864.14 1787,2814.86 1840.14,2761.72 1911.86,2761.72 1917.74,2767.6 1998.26,2767.6 2008,2757.86 2008,2644 2037,2615 2037,2576.25 D36.6@2027.6,2566.85 2037,2557.45 2037,2543.14 2021,2527.14 2021,2523.72 R169.2@2005,2507.72
LAN0_A-: D36.1 J22.3 R168.2 | length 752.9
  BOTTOM w4: J22.3@1840,2840 1856.4,2831.8 1875.3,2838.1 1886.5,2860.5 1880.86,2877.39 1863.65,2886 1823,2886 1797,2860 1797,2819 1844.28,2771.72 1907.72,2771.72 1913.6,2777.6 2002.4,2777.6 2018,2762 2018,2682.75 D36.1@2027.6,2673.15 2018,2663.55 2018,2648.14 2047,2619.14 2047,2539 2031,2523 2031,2516.72 R168.2@2040,2507.72
LAN0_B+: D36.3 J22.4 R167.2 | length 990.1
  TOP w4: J22.4@1790,2940 1795,2940 1810,2925 1810,2895 1790,2875 1760,2875 1745,2890 1745,2954.86 1769.14,2979 1911.86,2979 1962.36,2928.5 1997.36,2928.5 2026.65,2899.2 2026.65,2872.83 v1(2015.83,2862)
  BOTTOM w4: v1(2015.83,2862) 2026.65,2851.17 2026.65,2820.42 2111.21,2735.86 2111.21,2681.96 D36.3@2102.4,2673.15 2111.21,2664.34 2111.21,2622.21 2084,2595 2084,2538.5 2097.5,2525 2097.5,2520.22 R167.2@2085,2507.72
LAN0_B-: D36.4 J22.7 R166.2 | length 990.6
  TOP w4: J22.7@1640,2840 1664,2840 1735,2911 1735,2959 1765,2989 1916,2989 1966.5,2938.5 2001.5,2938.5 2036.65,2903.35 2036.65,2872.83 v1(2047.48,2862)
  BOTTOM w4: v1(2047.48,2862) 2036.65,2851.17 2036.65,2824.57 2121.21,2740.01 2121.21,2618.07 2094,2590.86 2094,2575.25 D36.4@2102.4,2566.85 2094,2558.45 2094,2542.64 2107.5,2529.14 2107.5,2520.22 R166.2@2120,2507.72
LAN0_C+: D35.6 J22.5 R165.2 | length 993.1
  BOTTOM w4: J22.5@1740,2840 1728.6,2843.8 1711,2879 1711,2886 1716.9,2891.9 1743,2904.95 1743,2959.86 1765.14,2982 1915,2982 1967,2930 2039.69,2930 2072.31,2897.39 2072.31,2815.78 2168,2720.09 2168,2635.86 2187,2616.86 2187,2600.86 2197,2590.86 2197,2576.25 D35.6@2187.6,2566.85 2197,2557.45 2197,2547.14 2192.43,2542.57 2185.05,2542.57 2172.5,2530.02 2172.5,2520.22 R165.2@2160,2507.72
LAN0_C-: D35.1 J22.6 R164.2 | length 992.3
  BOTTOM w4: J22.6@1690,2940 1708.16,2903.7 1714.15,2901.71 1733,2911.13 1733,2964 1761,2992 1919.14,2992 1971.14,2940 2043.84,2940 2082.31,2901.53 2082.31,2819.93 2178,2724.23 2178,2682.75 D35.1@2187.6,2673.15 2178,2663.55 2178,2640 2197,2621 2197,2605 2207,2595 2207,2543 2196.57,2532.57 2189.19,2532.57 2182.5,2525.88 2182.5,2520.22 R164.2@2195,2507.72
LAN0_D+: D35.3 J22.8 R163.2 | length 1304.6
  BOTTOM w4: J22.8@1590,2940 1600,2910 1589.6,2889.2 1569.8,2882.6 1559.65,2887.67 1546,2928.62 1546,2954.86 1602.14,3011 1931,3011 1980,2962 2048.71,2962 2101.31,2909.4 2101.31,2827.8 2196.88,2732.22 2238.63,2732.22 2272,2698.86 2272,2682.75 D35.3@2262.4,2673.15 2272,2663.55 2272,2627 2243.61,2598.6 2243.61,2542.25 2249.93,2535.93 2260,2525.86 2260,2518.58 2259.28,2517.86 2259.28,2517 R163.2@2250,2507.72
LAN0_D-: D35.4 J22.9 R162.2 | length 1304.2
  BOTTOM w4: J22.9@1540,2840 1555,2870 1552.67,2876.98 1552.27,2878.18 1551.87,2879.38 1551.47,2880.58 1536,2926.99 1536,2959 1598,3021 1935.14,3021 1984.14,2972 2052.85,2972 2111.31,2913.54 2111.31,2831.94 2201.02,2742.22 2242.77,2742.22 2282,2703 2282,2622.86 2253.61,2594.46 2253.61,2575.65 D35.4@2262.4,2566.85 2253.61,2558.05 2253.61,2546.4 2267.07,2532.93 2270,2530 2270,2522.72 R162.2@2285,2507.72
LANWAKEB: R154.2 R161.2 U15.21 | length 252.6
  BOTTOM w5: U15.21@2897.13,2226.26 2897.13,2204.73 2955,2146.86 R161.2@2955,2127.72 2936.07,2108.79 2936.07,2076.04 2928.33,2068.3 2928.33,2040.67 2941.28,2027.72 R154.2@2955,2027.72
LCD_BL_PWM_GPIO0_B7_D: M1.157 R75.1 R99.1 | length 3655.2
  TOP w5: R99.1@302.72,1600 302.72,1627.72 v1(315,1640) 315,1705.03 339.97,1730 410,1730 420,1740 420,1860 v1(320,1960) ; v1(2501.49,805.52) 2552.05,805.52 2577.54,780.02 2577.54,737.46 2597.05,717.95 M1.157@2597.05,707.87
  BOTTOM w5: R75.1@290,1892.28 320,1922.28 v1(320,1960) ; v1(315,1640) 315,1608.13 466.67,1456.46 466.67,1328.37 440.48,1302.18 440.48,1189.46 514.6,1115.34 697.24,1115.34 745.23,1163.33 920.96,1163.33 971.14,1113.14 1165.01,1113.14 1255.02,1203.15 1358.09,1203.15 1377.76,1183.48 1442.76,1183.48 1555,1071.23 1555,995.71 1694.39,856.33 2475.24,856.33 2501.49,830.08 v1(2501.49,805.52)
LCD_ON: J43.4 R98.2 R453.1 | length 598.6
  TOP w5: J43.4@110,1235.63 185,1310.63 185,1486.07 248.93,1550 R98.2@267.28,1550 292.28,1575 314.62,1575 324.67,1585.06 324.67,1623.75 335,1634.08 335,1692.72 R453.1@352.28,1710
LCD_PWM: J43.3 R99.2 | length 350.8
  TOP w5: J43.3@110,1314.37 165,1369.37 165,1480.21 267.28,1582.49 R99.2@267.28,1600
LCD_PWREN_H_GPIO0_B4_D: M1.154 R98.1 | length 3077.1
  TOP w5: R98.1@302.72,1550 303.76,1550 343,1589.24 v1(343,1611) ; M1.154@2478.94,707.87 2478.94,733.94 2488.88,743.88 v1(2488.88,755)
  BOTTOM w5: v1(343,1611) 343,1594.28 476.67,1460.61 476.67,1324.23 450.48,1298.04 450.48,1193.6 518.74,1125.34 693.1,1125.34 741.08,1173.33 925.1,1173.33 975.28,1123.14 1160.87,1123.14 1250.88,1213.15 1362.23,1213.15 1381.91,1193.48 1446.9,1193.48 1565,1075.38 1565,999.86 1698.53,866.33 2479.39,866.33 2519.82,825.89 2519.82,794.82 2488.88,763.88 v1(2488.88,755)
LED0/PHYAD0: C152.2 J23.11 R205.2 U17.24 | length 1786.2
  TOP w5: J23.11@794.17,3382.91 794.17,3344.97 814.14,3325 850.11,3325 1270,2905.11 1270,2877.27 C152.2@1312.28,2834.99 1332.27,2815 1387,2815 1396,2806 1396,2771.18 1311.06,2686.24 1311.06,2315.4 1236.4,2240.73 1236.4,2159.46 v1(1255,2140.86)
  BOTTOM w5: v1(1255,2140.86) 1255,2105 1245,2095 R205.2@1245,2077.72 1276.05,2108.77 U17.24@1276.05,2165.5
LED1/GPO: C112.1 J21.13 U15.26 | length 2084.7
  TOP w5: v1(2273.59,2743.69) 2273.59,2737.07 2225,2688.48 C112.1@2225,2687.72 2205,2707.72 2205,2960.86 2365,3120.86 2365,3342.1 J21.13@2324.2,3382.9
  BOTTOM w5: v1(2273.59,2743.69) 2364.28,2653 2541,2653 2586.37,2607.63 2614.63,2607.63 2652.5,2569.77 2652.5,2400 2567.5,2315 2567.5,2170.86 2586.08,2152.28 2689.77,2152.28 2716.43,2178.93 2763.96,2178.93 2778.33,2193.3 2778.33,2233.33 2810.63,2265.63 U15.26@2826.26,2265.63
LED1/PHYAD1: C150.1 J23.9 R200.2 U17.25 | length 1753.6
  TOP w5: J23.9@1215.83,3382.91 1178.74,3420 1100,3420 1025,3345 1025,3164.25 1274.24,2915.01 C150.1@1312.28,2915.01 R200.2@1312.28,2875 1332.28,2855 1390,2855 1406,2839 1406,2767.04 1321.06,2682.1 1321.06,2311.25 1254.72,2244.92 v1(1254.72,2167.51)
  BOTTOM w5: U17.25@1250.5,2191.05 1236.05,2191.05 1230,2185 1230,2172.51 1235,2167.51 v1(1254.72,2167.51)
LED2/LED1: C113.1 J21.12 U15.25 | length 2098.6
  TOP w5: v1(2621.35,2575) 2621.35,2676.66 2600,2698 2600,2765 2667,2832 2667,2859 2690,2882 2730,2882 2758,2854 2758,2806 2772.01,2791.99 2850.99,2791.99 2867.28,2808.28 C113.1@2867.28,2845.01 2867.28,2846.57 2609,3104.86 2609,3237.14 2645.8,3273.94 J21.12@2645.8,3382.9
  BOTTOM w5: v1(2621.35,2575) 2642.5,2553.85 2642.5,2404.14 2557.5,2319.14 2557.5,2166.72 2581.94,2142.28 2693.91,2142.28 2720.57,2168.93 2768.1,2168.93 2788.33,2189.16 2788.33,2229.18 2809.03,2249.88 U15.25@2826.26,2249.88
MAC_MDC_: C151.2 R203.2 U17.22 | length 2509.3
  BOTTOM w5: U17.22@1315.45,2165.5 1315.45,2086.55 1325,2077 1325,1994.08 1343.08,1976 1408.14,1976 1521.04,1863.11 1730.52,1863.11 1971.7,1621.92 2420.9,1621.92 2619.01,1820.04 3004.04,1820.04 3045,1861 3045,1878.44 3106.35,1939.8 3106.35,1993.79 3117.56,2005 3175,2005 3207.28,2037.28 C151.2@3207.28,2065.01 3229,2086.73 3229,2096.28 R203.2@3240,2107.28
MAC_MDIO: R202.2 R207.2 U17.23 | length 2384.5
  BOTTOM w5: U17.23@1295.75,2165.5 1295.75,2106.75 1285,2096 R207.2@1285,2077.72 1299.28,2077.72 1306,2071 1306,1994 1336,1964 1404,1964 1516,1852 1723.48,1852 1965.56,1609.92 2426.04,1609.92 2624.16,1808.04 3010.04,1808.04 3049.66,1847.66 3068.66,1847.66 3130,1909 3130,1914 3144,1928 3144,1961.28 R202.2@3162.72,1980
MIC1_IN: C1049.2 D65.1 J36.1 R388.2 | length 3741.6
  TOP w10: C1049.2@3457.72,1410.01 3475.33,1427.62 v1(3475.33,1458.33) ; v1(3630,1480) 3642.5,1467.5 4221.5,1467.5 4313.5,1375.5 4449.18,1375.5 4480.33,1406.65 v1(4760,1406.65) ; v1(5154.61,3157) J36.1@5154.61,3205
  BOTTOM w10: v1(3475.33,1458.33) 3475.33,1475.33 3485,1485 3613.33,1485 3618.33,1480 v1(3630,1480) ; v1(4760,1406.65) 4786.35,1433 4802.79,1433 4975.65,1605.86 4975.65,1627.97 4992.5,1644.82 4992.5,1662.5 5142.38,1812.38 5142.38,2614.17 4944,2812.55 4944,3050 5070,3176 R388.2@5070,3237.28 5092.82,3237.28 5094,3236.1 D65.1@5115,3236.1 5154.61,3196.5 v1(5154.61,3157)
MIC2_IN: C1050.2 D69.1 J37.1 R387.2 | length 4348.5
  TOP w10: C1050.2@3457.72,1370.01 3502.08,1414.36 3502.08,1459.38 v1(3501.96,1459.49) ; v1(3597,1458.33) 3605.33,1450 4213.11,1450 4304.11,1359 4457,1359 4483.83,1385.83 4770.83,1385.83 v1(4790,1405) ; J37.1@4627.36,3441.73 4577.73,3441.73 4556,3420 4556,2947 4511.1,2902.1 D69.1@4511.1,2865 4511.1,2840.9 4512.28,2839.72 R387.2@4512.28,2820 4512.28,2691.72 4529,2675 5124,2675 v1(5146,2653)
  BOTTOM w10: v1(3501.96,1459.49) 3503.13,1458.33 v1(3597,1458.33) ; v1(4790,1405) 4803.32,1405 4994.5,1596.18 4994.5,1625.61 5007.5,1638.61 5007.5,1652.5 5159.38,1804.38 5159.38,2639.62 v1(5146,2653)
MIPI_CSI1_RX0_D2N: J19.11 R1175.5 | length 1238.1
  TOP w4: J19.11@779.53,267.01 779.53,236.18 774.68,231.34 774.68,211.78 v1(785.76,200.7)
  BOTTOM w4: v1(785.76,200.7) 778,208.46 778,213.86 783.14,219 823.21,219 849.85,192.37 1422.71,192.37 1451.35,221 1722.14,221 1825.67,324.52 1825.67,333.81 1831.5,339.64 R1175.5@1831.5,355.31
MIPI_CSI1_RX0_D2P: J19.12 R1175.6 | length 1240.4
  TOP w4: v1(754.11,200.7) 764.68,211.27 764.68,231.34 759.84,236.18 J19.12@759.84,267.01
  BOTTOM w4: v1(754.11,200.7) 768,214.59 768,218 779,229 827.36,229 853.99,202.37 1418.57,202.37 1447.21,231 1718,231 1815.67,328.67 1815.67,333.81 1809.84,339.63 R1175.6@1809.84,355.31
MIPI_CSI1_RX0_D3N: J19.14 R1175.7 | length 1271.4
  TOP w4: J19.14@720.47,267.01 720.47,236.18 715.63,231.34 715.63,211.62 v1(726.46,200.79)
  BOTTOM w4: v1(726.46,200.79) 724.2,200.79 715.63,209.37 715.63,231.63 732,248 835.23,248 861.86,221.37 1410.7,221.37 1439.34,250 1709.14,250 1784.33,325.19 1784.33,333.81 1790.16,339.64 R1175.7@1790.16,355.31
MIPI_CSI1_RX0_D3P: J19.15 R1175.8 | length 1272.4
  TOP w4: v1(694.8,200.79) 705.63,211.62 705.63,231.34 700.79,236.18 J19.15@700.79,267.01
  BOTTOM w4: v1(694.8,200.79) 698.79,200.79 705.63,207.63 705.63,235.77 727.86,258 839.37,258 866,231.37 1406.56,231.37 1435.19,260 1705,260 1774.33,329.33 1774.33,333.81 1768.5,339.63 R1175.8@1768.5,355.31
MIPI_CSI2_RX0_D2N: J18.11 R1176.8 | length 112
  TOP w4: J18.11@1783.58,267.01 1783.58,295.44 1788.14,300 1794.7,300 1829,334.3 1829,350 1831.5,352.5 R1176.8@1831.5,355.31
MIPI_CSI2_RX0_D2P: J18.12 R1176.7 | length 118.8
  TOP w4: J18.12@1763.9,267.01 1763.9,289.9 1784,310 1790.56,310 1819,338.44 1819,341.67 1809.84,350.82 R1176.7@1809.84,355.31
MIPI_CSI2_RX0_D3N: J18.14 R1176.6 | length 132.9
  TOP w4: J18.14@1724.53,267.01 1724.53,286.47 1719.68,291.32 1719.68,295.54 1746.14,322 1769,322 1785,338 1785,346 1790.16,351.16 R1176.6@1790.16,355.31
MIPI_CSI2_RX0_D3P: J18.15 R1176.5 | length 133.4
  TOP w4: J18.15@1704.84,267.01 1704.84,286.84 1709.68,291.68 1709.68,299.68 1742,332 1764.86,332 1775,342.14 1775,346 1768.5,352.5 R1176.5@1768.5,355.31
MIPI_CSI_RX0_CLK0N: J18.5 M1.137 | length 515
  TOP w4: M1.137@1809.65,707.87 1809.65,694.65 1794.96,679.96 1794.96,674.3 1858,611.27 1858,559.14 1897.9,519.24 1897.9,395.45 1883.25,380.8 1883.25,373.8 v1(1894.08,362.97) ; J18.5@1901.69,267.01 1901.69,303.69 v1(1905,307)
  BOTTOM w4: v1(1894.08,362.97) 1883.25,352.14 1883.25,341.75 1895,330 1895,317 v1(1905,307)
MIPI_CSI_RX0_CLK0P: J18.6 M1.136 | length 516.5
  TOP w4: M1.136@1770.28,707.87 1770.28,694.72 1784.96,680.04 1784.96,670.16 1848,607.12 1848,555 1887.9,515.1 1887.9,399.6 1873.25,384.94 1873.25,373.8 v1(1862.42,362.97) ; v1(1875,307) 1882.01,299.99 J18.6@1882.01,267.01
  BOTTOM w4: v1(1862.42,362.97) 1873.25,352.14 1873.25,337.61 1885,325.86 1885,317 v1(1875,307)
MIPI_CSI_RX0_CLK1N: J19.17 M1.131 | length 1633
  TOP w4: J19.17@661.42,267.01 661.42,297.84 656.58,302.68 656.58,312.48 609.63,359.43 609.63,380.49 573.43,416.69 573.43,568.31 649.12,644 747,644 757,654 757,665.52 v1(766.83,675.35) ; v1(1569.57,770.09) 1559,759.52 1559,739 1573.42,724.58 M1.131@1573.42,707.87
  BOTTOM w4: v1(766.83,675.35) 756,686.17 756,691.86 763.99,699.85 979.83,699.85 1005.99,726 1057.91,726 1062.91,731 1468.85,731 1478.71,740.86 1478.71,785.57 1483.14,790 1497.86,790 1502.71,785.15 1502.71,740.86 1512.57,731 1548,731 1558.74,741.74 1558.74,759.26 v1(1569.57,770.09)
MIPI_CSI_RX0_CLK1P: J19.18 M1.130 | length 1634.3
  TOP w4: J19.18@641.73,267.01 641.73,297.84 646.58,302.68 646.58,308.34 599.63,355.28 599.63,376.35 563.43,412.55 563.43,572.45 644.98,654 742.86,654 747,658.14 747,663.52 v1(735.17,675.35) ; M1.130@1534.06,707.87 1534.06,723.05 1549,738 1549,759 v1(1537.91,770.09)
  BOTTOM w4: v1(735.17,675.35) 746,686.17 746,696 759.85,709.85 975.69,709.85 1001.84,736 1053.77,736 1058.77,741 1464.71,741 1468.71,745 1468.71,789.71 1479,800 1502,800 1512.71,789.29 1512.71,745 1516.71,741 1543.86,741 1548.74,745.88 1548.74,759.26 v1(1537.91,770.09)
MIPI_CSI_RX0_D0N: J18.2 M1.141 | length 492.4
  TOP w4: J18.2@1960.75,267.01 1960.75,297.84 1955.9,302.68 1955.9,339.25 1962,345.34 1962,355.25 1955.9,361.34 1955.9,371.25 1962,377.34 1962,387.25 1955.9,393.34 1955.9,460.23 1999,503.33 1999,636 1957,678 1957,682 1967.13,692.13 M1.141@1967.13,707.87
MIPI_CSI_RX0_D0P: J18.3 M1.140 | length 492.5
  TOP w4: M1.140@1927.76,707.87 1927.76,692.24 1933,687 1944,687 1947,684 1947,673.86 1989,631.86 1989,507.47 1945.9,464.38 1945.9,302.68 1941.06,297.84 J18.3@1941.06,267.01
MIPI_CSI_RX0_D1N: J18.8 M1.139 | length 583.6
  TOP w4: J18.8@1842.64,267.01 1842.64,288.36 1837.8,293.21 1837.8,302.08 1865.86,330.14 1909.68,330.14 1926.9,347.37 1926.9,472.25 1970,515.34 1970,606 1951,625 1926.55,625 1873.7,677.84 1873.7,685.7 1888.39,700.39 M1.139@1888.39,707.87
MIPI_CSI_RX0_D1P: J18.9 M1.138 | length 583.6
  TOP w4: J18.9@1822.95,267.01 1822.95,287.95 1827.8,292.8 1827.8,306.22 1861.72,340.14 1905.53,340.14 1916.9,351.52 1916.9,476.39 1960,519.49 1960,601.86 1946.86,615 1922.4,615 1863.7,673.7 1863.7,684.3 1849.02,698.98 M1.138@1849.02,707.87
MIPI_CSI_RX0_D2N: M1.135 R1175.4 R1176.1 | length 404.8
  TOP w4: M1.135@1730.91,707.87 1730.91,697.91 1720,687 1720,684.14 1793,611.14 1793,524.14 1829.77,487.38 1829.77,435.23 v1(1840,425) 1840,424.35 1831.5,415.85 R1176.1@1831.5,394.69
  BOTTOM w4: R1175.4@1831.5,394.69 1831.5,416.5 v1(1840,425)
MIPI_CSI_RX0_D2P: M1.134 R1175.3 R1176.2 | length 405
  TOP w4: M1.134@1691.54,707.87 1691.54,697.46 1701,688 1707,688 1710,685 1710,680 1783,607 1783,520 1819.77,483.23 1819.77,435.23 1809.53,425 v1(1809.53,424.53) 1808.96,424.53 1809.84,423.64 R1176.2@1809.84,394.69
  BOTTOM w4: v1(1809.53,424.53) 1809.84,424.22 R1175.3@1809.84,394.69
MIPI_CSI_RX0_D3N: M1.133 R1175.2 R1176.3 | length 420.7
  TOP w4: M1.133@1652.16,707.87 1652.16,701.16 1633,682 1633,666 1669,630 1669,570.14 1770,469.14 1770,435 v1(1780,425) 1780,420 1790.16,409.84 R1176.3@1790.16,394.69
  BOTTOM w4: v1(1780,425) 1780,420 1790.16,409.84 R1175.2@1790.16,394.69
MIPI_CSI_RX0_D3P: M1.132 R1175.1 R1176.4 | length 423.9
  TOP w4: M1.132@1612.8,707.87 1612.8,700.21 1623,690 1623,661.86 1659,625.86 1659,566 1760,465 1760,435 v1(1750,425) 1750,420 1768.5,401.5 R1176.4@1768.5,394.69
  BOTTOM w4: v1(1750,425) 1750,420 1768.5,401.5 R1175.1@1768.5,394.69
MIPI_CSI_RX1_CLK0N: J20.17 M1.125 | length 2100.9
  TOP w4: J20.17@116.03,720.74 107.74,720.74 104.87,717.87 100.27,717.87 97.81,720.33 97.81,885.79 132.03,920 249,920 286,883 460.82,883 597.82,911.89 629.17,911.89 v1(640,901.07) ; v1(1413,920.39) 1420.39,920.39 1424.1,924.1 1424.1,937 1428.1,941 1446.61,941 1450.61,937 1450.61,922.39 1456.46,916.53 M1.125@1482.87,916.53
  BOTTOM w4: v1(640,901.07) 650.82,911.89 660.97,911.89 670,920.93 670,960.86 684.74,975.6 739.76,975.6 761.52,953.84 761.52,864.12 802.64,823 937.03,823 986.03,872 1219.14,872 1229,881.86 1229,919.17 1233,923.17 1249,923.17 1253,919.17 1253,881.86 1262.86,872 1287.14,872 1297,881.86 1297,944.03 1301,948.03 1317,948.03 1321,944.03 1321,881.86 1330.86,872 1357,872 1367.17,882.17 1367.17,911.03 1387.36,931.22 1402.17,931.22 v1(1413,920.39)
MIPI_CSI_RX1_CLK0P: J20.15 M1.124 | length 2101.7
  TOP w4: J20.15@116.03,705 107,705 104.13,707.87 96.13,707.87 87.81,716.18 87.81,889.93 127.89,930 253.14,930 290.14,893 459.77,893 596.77,921.89 629.17,921.89 v1(640,932.72) ; v1(1413,952.05) 1414.05,951 1452,951 1456.91,955.91 M1.124@1482.87,955.91
  BOTTOM w4: v1(640,932.72) 650.82,921.89 656.82,921.89 660,925.07 660,965 680.6,985.6 743.9,985.6 771.52,957.99 771.52,868.27 806.79,833 932.88,833 981.88,882 1215,882 1219,886 1219,923.32 1228.86,933.17 1253.14,933.17 1263,923.32 1263,886 1267,882 1283,882 1287,886 1287,948.17 1296.86,958.03 1321.14,958.03 1331,948.17 1331,886 1335,882 1352.86,882 1357.17,886.32 1357.17,915.17 1383.22,941.22 1402.17,941.22 v1(1413,952.05)
MIPI_CSI_RX1_CLK1N: M1.119
MIPI_CSI_RX1_CLK1P: M1.118
MIPI_CSI_RX1_D0N: J20.13 M1.129 | length 2045.1
  TOP w4: J20.13@116.03,689.25 104.25,689.25 102,687 87.14,687 74,700.14 74,902.86 120.14,949 225.01,949 299.19,1023.17 337.32,1023.17 369.14,1055 471.07,1055 475.07,1051 475.07,1008.86 484.93,999 509.21,999 519.07,1008.86 519.07,1051 523.07,1055 568.86,1055 666,957.86 666,939 674.5,930.5 688.87,916.13 688.87,880.83 v1(678.04,870) ; v1(1413,762.91) 1425.91,762.91 1429,766 1429,778 1434,783 1448,783 1453.5,777.5 1453.5,763.5 1457.94,759.05 M1.129@1482.87,759.05
  BOTTOM w4: v1(678.04,870) 688.87,859.17 688.87,846.13 770,765 1032.87,765 1045.97,778.1 1362.76,778.1 1368.95,771.91 1404.01,771.91 v1(1413,762.91)
MIPI_CSI_RX1_D0P: J20.11 M1.128 | length 2055.3
  TOP w4: J20.11@116.03,673.5 105.5,673.5 102,677 83,677 64,696 64,907 116,959 220.87,959 295.05,1033.17 333.17,1033.17 365,1065 475.21,1065 485.07,1055.14 485.07,1013 489.07,1009 505.07,1009 509.07,1013 509.07,1055.14 518.92,1065 573,1065 676,962 676,943.14 698.87,920.28 698.87,880.83 v1(709.69,870) ; v1(1413,794.57) 1414.57,793 1459,793 1464.42,798.42 M1.128@1482.87,798.42
  BOTTOM w4: v1(709.69,870) 698.87,859.17 698.87,850.28 774.14,775 1028.73,775 1041.83,788.1 1366.9,788.1 1373.09,781.91 1409.91,781.91 1413,785 v1(1413,794.57)
MIPI_CSI_RX1_D1N: J20.9 M1.127 | length 2049.8
  TOP w4: J20.9@116.03,657.75 108.75,657.75 105.88,654.88 77.12,654.88 49,683 49,917 111.57,979.57 262.14,1027.14 287.17,1052.17 322.95,1052.17 354.77,1084 598.86,1084 711.2,971.66 711.2,961.88 v1(700.37,951.05) ; v1(1413,841.65) 1421.65,841.65 1425.66,845.66 1425.66,856.66 1431,862 1444,862 1448.65,857.34 1448.65,841.34 1452.2,837.79 M1.127@1482.87,837.79
  BOTTOM w4: v1(700.37,951.05) 711.2,940.23 711.2,928.93 732.52,879.93 732.52,852.11 790.63,794 949.04,794 998.04,843 1388,843 1397.48,852.48 1402.17,852.48 v1(1413,841.65)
